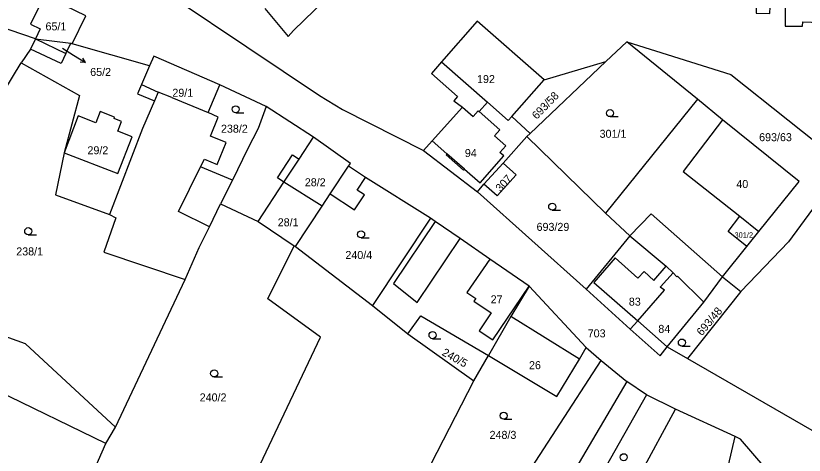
# Model space of a CAD drawing. Extents: x -747333 to -743907, y -1134120 to -1130051.
# Drawn here: x -746528 to -746360.5, y -1132212.3 to -1132118.9 of the extents above; entities that cross this region are included whole.
import ezdxf

# ---------------------------------------------------------------- set-up
doc = ezdxf.new("R2010")
doc.units = 0
for name, color, linetype in [('Hranice parcel', 7, 'Continuous'), ('Parcelní čísla', 7, 'Continuous'), ('Pop  PČ popisy', 7, 'Continuous'), ('Vnitřní kresba', 7, 'Continuous'), ('Značky kultur', 7, 'Continuous')]:
    doc.layers.add(name, color=color, linetype=linetype)

msp = doc.modelspace()

# ---------------------------------------------------------------- linework, layer by layer
at = {"layer": 'Hranice parcel'}
for p, q in [((-746523.8, -1132123.84), (-746533.15, -1132120.64)), ((-746523.8, -1132123.84), (-746524.84, -1132126.03)), ((-746523.8, -1132123.84), (-746516.28, -1132124.76)), ((-746516.28, -1132124.76), (-746515.99, -1132124.9)), ((-746499.55, -1132129.55), (-746515.99, -1132124.9)), ((-746398.24, -1132124.43), (-746402.67, -1132128.64)), ((-746383.2, -1132136.66), (-746398.24, -1132124.43)), ((-746398.24, -1132124.43), (-746376.13, -1132131.39)), ((-746524.84, -1132126.03), (-746526.85, -1132128.93)), ((-746402.67, -1132128.64), (-746418.74, -1132143.92)), ((-746415.8, -1132132.54), (-746402.67, -1132128.64)), ((-746474.8, -1132138.2), (-746484.6, -1132133.59)), ((-746422.65, -1132140.36), (-746415.8, -1132132.54)), ((-746383.2, -1132136.66), (-746402.78, -1132160.86)), ((-746464.75, -1132144.73), (-746474.8, -1132138.2)), ((-746433.12, -1132138.33), (-746439.53, -1132145.49)), ((-746418.74, -1132143.92), (-746422.65, -1132140.36)), ((-746419.45, -1132144.58), (-746418.74, -1132143.92)), ((-746439.53, -1132145.49), (-746441.38, -1132147.52)), ((-746424.49, -1132150.27), (-746419.45, -1132144.58)), ((-746419.45, -1132144.58), (-746402.78, -1132160.86)), ((-746441.38, -1132147.52), (-746429.95, -1132156.33)), ((-746428.57, -1132154.69), (-746424.49, -1132150.27)), ((-746481.98, -1132153.82), (-746484.47, -1132158.9)), ((-746439.9, -1132161.92), (-746453.69, -1132153.29)), ((-746429.95, -1132156.33), (-746428.57, -1132154.69)), ((-746370.18, -1132164.75), (-746361.64, -1132154.17)), ((-746429.95, -1132156.33), (-746406.86, -1132176.98)), ((-746468.6, -1132167.97), (-746462.92, -1132159.41)), ((-746439.9, -1132161.92), (-746452.21, -1132180.46)), ((-746402.78, -1132160.86), (-746397.61, -1132165.68)), ((-746397.61, -1132165.68), (-746406.86, -1132176.98)), ((-746397.61, -1132165.68), (-746389.84, -1132172.12)), ((-746372.76, -1132167.96), (-746370.18, -1132164.75)), ((-746468.85, -1132167.8), (-746468.6, -1132167.97)), ((-746468.6, -1132167.97), (-746452.21, -1132180.46)), ((-746377.93, -1132174.38), (-746372.76, -1132167.96)), ((-746389.84, -1132172.12), (-746388.41, -1132173.53)), ((-746506.79, -1132206.34), (-746492.01, -1132174.94)), ((-746381.9, -1132179.76), (-746377.93, -1132174.38)), ((-746377.93, -1132174.38), (-746374.04, -1132177.52)), ((-746406.82, -1132189.39), (-746418.95, -1132176.36)), ((-746406.86, -1132176.98), (-746397.51, -1132185.52)), ((-746374.04, -1132177.52), (-746385.31, -1132191.74)), ((-746452.21, -1132180.46), (-746444.75, -1132186.48)), ((-746389.67, -1132189.29), (-746381.9, -1132179.76)), ((-746508.81, -1132209.8), (-746568.17, -1132180.98)), ((-746397.51, -1132185.52), (-746395.9, -1132183.77)), ((-746444.75, -1132186.48), (-746430.73, -1132196.48)), ((-746406.82, -1132189.39), (-746403.66, -1132192.14)), ((-746389.67, -1132189.29), (-746385.31, -1132191.74)), ((-746430.73, -1132196.48), (-746427.61, -1132191.08)), ((-746403.66, -1132192.14), (-746398.19, -1132196.61)), ((-746385.31, -1132191.74), (-746349.14, -1132212.69)), ((-746439.77, -1132214.12), (-746430.73, -1132196.48)), ((-746398.19, -1132196.61), (-746414.98, -1132225.06)), ((-746394.06, -1132199.47), (-746398.19, -1132196.61)), ((-746394.06, -1132199.47), (-746409.61, -1132226.97)), ((-746387.86, -1132202.51), (-746394.06, -1132199.47)), ((-746402.53, -1132229.49), (-746387.86, -1132202.51)), ((-746375.2, -1132208.32), (-746387.86, -1132202.51)), ((-746508.81, -1132209.8), (-746506.79, -1132206.34)), ((-746512.76, -1132218.71), (-746508.81, -1132209.8))]:
    msp.add_line(p, q, dxfattribs=at)
for points in [[(-746512.89, -1132094.09), (-746509.52, -1132104.89), (-746463.45, -1132135.88), (-746458.58, -1132138.82), (-746441.38, -1132147.52)], [(-746355.58, -1132109.28), (-746360.59, -1132109.08), (-746360.16, -1132101.31), (-746366.14, -1132100.93), (-746366.2, -1132102.85), (-746370.91, -1132102.78), (-746370.97, -1132104.58), (-746376.22, -1132104.42), (-746376.7, -1132109.89), (-746374.83, -1132110.1), (-746374.9, -1132112.66), (-746370.69, -1132112.9), (-746370.75, -1132118.4), (-746367.87, -1132118.47), (-746367.81, -1132117.06), (-746364.58, -1132117.06), (-746364.61, -1132121.16), (-746360.9, -1132121.16), (-746360.86, -1132120.23), (-746355.36, -1132120.45)], [(-746475.1, -1132117.39), (-746470.12, -1132123.36), (-746469.01, -1132122.04), (-746460.04, -1132113.37)], [(-746515.99, -1132124.9), (-746513.12, -1132118.91), (-746521.86, -1132114.62), (-746524.85, -1132120.71), (-746522.77, -1132121.69), (-746523.8, -1132123.84)], [(-746415.8, -1132132.54), (-746430, -1132120.09), (-746437.54, -1132128.72), (-746439.72, -1132131.22), (-746434.15, -1132136.09), (-746434.93, -1132136.99), (-746433.12, -1132138.33)], [(-746523.8, -1132123.84), (-746517.31, -1132126.95), (-746516.28, -1132124.76)], [(-746543.9, -1132155.07), (-746536.7, -1132145.21), (-746526.85, -1132128.93)], [(-746526.85, -1132128.93), (-746514.46, -1132135.87), (-746517.68, -1132148.02), (-746519.55, -1132156.97), (-746508.03, -1132161.18)], [(-746484.6, -1132133.59), (-746498.66, -1132127.5), (-746499.55, -1132129.55)], [(-746499.55, -1132129.55), (-746501.28, -1132133.56), (-746497.76, -1132135.18), (-746498.53, -1132136.98), (-746501.07, -1132142.89), (-746508.03, -1132161.18)], [(-746376.13, -1132131.39), (-746351.94, -1132150.67), (-746363.92, -1132166.96), (-746374.04, -1132177.52)], [(-746481.98, -1132153.82), (-746488.73, -1132150.99), (-746487.86, -1132149.42), (-746485.17, -1132150.55), (-746483.26, -1132145.87), (-746486.65, -1132144.48), (-746485, -1132140.49), (-746487.14, -1132139.46), (-746484.6, -1132133.59)], [(-746433.12, -1132138.33), (-746430.85, -1132140.35), (-746429.75, -1132139.12), (-746429.6, -1132139.26), (-746427.83, -1132137.27), (-746423.38, -1132141.19), (-746422.65, -1132140.36)], [(-746361.64, -1132154.17), (-746377.92, -1132141.05), (-746383.2, -1132136.66)], [(-746474.8, -1132138.2), (-746476.52, -1132142.87), (-746478.77, -1132147.26), (-746481.98, -1132153.82)], [(-746462.92, -1132159.41), (-746471.01, -1132154.29), (-746467.81, -1132149.4), (-746464.75, -1132144.73)], [(-746453.69, -1132153.29), (-746457.28, -1132150.91), (-746456.89, -1132150.33), (-746464.75, -1132144.73)], [(-746424.49, -1132150.27), (-746421.7, -1132152.74), (-746425.77, -1132157.17), (-746428.57, -1132154.69)], [(-746456.05, -1132160.19), (-746453.92, -1132156.98), (-746455.46, -1132155.96), (-746453.69, -1132153.29)], [(-746462.92, -1132159.41), (-746461.18, -1132156.79), (-746456.05, -1132160.19)], [(-746492.01, -1132174.94), (-746489.02, -1132168.19), (-746486.86, -1132163.77), (-746484.47, -1132158.9)], [(-746484.47, -1132158.9), (-746476.47, -1132162.64), (-746468.85, -1132167.8)], [(-746508.03, -1132161.18), (-746506.73, -1132161.88), (-746509.28, -1132169.18), (-746492.01, -1132174.94)], [(-746433.6, -1132166.24), (-746438.91, -1132162.6), (-746439.9, -1132161.92)], [(-746372.76, -1132167.96), (-746376.72, -1132164.77), (-746374.25, -1132161.52), (-746370.18, -1132164.75)], [(-746418.95, -1132176.36), (-746427.27, -1132170.61), (-746433.6, -1132166.24)], [(-746488.24, -1132239.95), (-746463.28, -1132187.24), (-746474.43, -1132179.05), (-746468.85, -1132167.8)], [(-746395.9, -1132183.77), (-746390.21, -1132177.25), (-746391.15, -1132176.62), (-746391.07, -1132176.53), (-746388.41, -1132173.53)], [(-746388.41, -1132173.53), (-746387.63, -1132174.36), (-746387.45, -1132174.22), (-746381.9, -1132179.76)], [(-746506.79, -1132206.34), (-746525.9, -1132188.66), (-746565.04, -1132174.52)], [(-746418.95, -1132176.36), (-746422.87, -1132182.82), (-746427.61, -1132191.08)], [(-746444.75, -1132186.48), (-746441.98, -1132182.67), (-746427.61, -1132191.08)], [(-746397.51, -1132185.52), (-746391.16, -1132191.17), (-746389.67, -1132189.29)], [(-746427.61, -1132191.08), (-746413.07, -1132199.82), (-746408.27, -1132191.87), (-746406.82, -1132189.39)], [(-746439.77, -1132214.12), (-746422.02, -1132220.4), (-746413.23, -1132206.88), (-746403.66, -1132192.14)], [(-746383.65, -1132246.38), (-746379.95, -1132228.73), (-746375.2, -1132208.32)], [(-746361.01, -1132224.1), (-746374.1, -1132208.89), (-746375.2, -1132208.32)]]:
    msp.add_lwpolyline(points, dxfattribs=at)
at = {"layer": 'Pop  PČ popisy'}
for p, q in [((-746518.05, -1132125.79), (-746515.7, -1132127.28)), ((-746515.7, -1132127.28), (-746513.155, -1132128.87)), ((-746513.155, -1132128.87), (-746514.27, -1132128.764)), ((-746513.155, -1132128.87), (-746513.739, -1132127.915))]:
    msp.add_line(p, q, dxfattribs=at)
at = {"layer": 'Vnitřní kresba'}
for p, q in [((-746518.33, -1132129.1), (-746524.84, -1132126.03)), ((-746517.31, -1132126.95), (-746518.33, -1132129.1)), ((-746437.54, -1132128.72), (-746427.83, -1132137.27)), ((-746501.28, -1132133.56), (-746502.12, -1132135.48)), ((-746502.12, -1132135.48), (-746498.53, -1132136.98)), ((-746494.82, -1132136.26), (-746497.76, -1132135.18)), ((-746494.82, -1132136.26), (-746487.14, -1132139.46)), ((-746514.71, -1132140.21), (-746517.68, -1132148.02)), ((-746510.97, -1132141.65), (-746514.71, -1132140.21)), ((-746510.06, -1132139.27), (-746510.97, -1132141.65)), ((-746506.97, -1132140.46), (-746510.06, -1132139.27)), ((-746507.1, -1132140.78), (-746506.97, -1132140.46)), ((-746429.6, -1132139.26), (-746425.18, -1132143.19)), ((-746505.51, -1132141.4), (-746507.1, -1132140.78)), ((-746506.31, -1132143.45), (-746505.51, -1132141.4)), ((-746377.92, -1132141.05), (-746386.25, -1132151.99)), ((-746503.27, -1132144.62), (-746506.31, -1132143.45)), ((-746425.18, -1132143.19), (-746426.28, -1132144.42)), ((-746506.28, -1132152.42), (-746503.27, -1132144.62)), ((-746439.53, -1132145.49), (-746436.41, -1132148.24)), ((-746426.28, -1132144.42), (-746423.89, -1132146.55)), ((-746425.15, -1132147.97), (-746423.89, -1132146.55)), ((-746517.68, -1132148.02), (-746506.28, -1132152.42)), ((-746472.4, -1132153.39), (-746469.22, -1132148.47)), ((-746469.22, -1132148.47), (-746467.81, -1132149.4)), ((-746436.41, -1132148.24), (-746436.59, -1132148.45)), ((-746436.59, -1132148.45), (-746432.87, -1132151.74)), ((-746432.68, -1132151.53), (-746436.41, -1132148.24)), ((-746429.39, -1132154.44), (-746424.32, -1132148.7)), ((-746424.32, -1132148.7), (-746425.15, -1132147.97)), ((-746493.39, -1132160.49), (-746488.73, -1132150.99)), ((-746461.18, -1132156.79), (-746457.28, -1132150.91)), ((-746432.87, -1132151.74), (-746432.68, -1132151.53)), ((-746432.68, -1132151.53), (-746429.39, -1132154.44)), ((-746386.25, -1132151.99), (-746374.25, -1132161.52)), ((-746471.01, -1132154.29), (-746472.4, -1132153.39)), ((-746476.47, -1132162.64), (-746471.01, -1132154.29)), ((-746486.86, -1132163.77), (-746493.39, -1132160.49)), ((-746393.06, -1132161.01), (-746397.61, -1132165.68)), ((-746377.93, -1132174.38), (-746393.06, -1132161.01)), ((-746438.91, -1132162.6), (-746447.75, -1132175.82)), ((-746442.73, -1132179.87), (-746433.6, -1132166.24)), ((-746400.72, -1132170.37), (-746405.23, -1132175.59)), ((-746395.85, -1132174.69), (-746400.72, -1132170.37)), ((-746392.49, -1132175.17), (-746389.84, -1132172.12)), ((-746394.53, -1132173.23), (-746395.85, -1132174.69)), ((-746392.49, -1132175.17), (-746394.53, -1132173.23)), ((-746405.23, -1132175.59), (-746395.9, -1132183.77)), ((-746447.75, -1132175.82), (-746442.73, -1132179.87)), ((-746408.27, -1132191.87), (-746422.87, -1132182.82)), ((-746395.9, -1132183.77), (-746389.67, -1132189.29))]:
    msp.add_line(p, q, dxfattribs=at)
msp.add_lwpolyline([(-746427.27, -1132170.61), (-746432.16, -1132177.73), (-746430.31, -1132178.99), (-746430.7, -1132179.57), (-746427.03, -1132182.07), (-746429.6, -1132185.84), (-746426.7, -1132187.81), (-746418.95, -1132176.36)], dxfattribs=at)
at = {"layer": 'Značky kultur'}
for p, q in [((-746481.263, -1132139.54), (-746479.513, -1132139.54)), ((-746401.783, -1132140.35), (-746400.033, -1132140.35)), ((-746414.053, -1132160.25), (-746412.303, -1132160.25)), ((-746525.323, -1132165.44), (-746523.573, -1132165.44)), ((-746454.643, -1132166.12), (-746452.893, -1132166.12)), ((-746439.463, -1132187.53), (-746437.713, -1132187.53)), ((-746386.523, -1132189.11), (-746384.773, -1132189.11)), ((-746485.833, -1132195.67), (-746484.083, -1132195.67)), ((-746424.363, -1132204.64), (-746422.613, -1132204.64))]:
    msp.add_line(p, q, dxfattribs=at)
for centre in [(-746481.263, -1132138.79), (-746401.783, -1132139.6), (-746414.053, -1132159.5), (-746525.323, -1132164.69), (-746454.643, -1132165.37), (-746439.463, -1132186.78), (-746386.523, -1132188.36), (-746485.833, -1132194.92), (-746424.363, -1132203.89), (-746398.873, -1132212.72)]:
    msp.add_circle(centre, 0.75, dxfattribs=at)

# ---------------------------------------------------------------- texts
at = {"layer": 'Parcelní čísla'}
for s, height, p in [('65/1', 1.7, (-746521.651, -1132122.03)), ('65/2', 1.7, (-746512.16, -1132131.713)), ('192', 1.7, (-746430.02, -1132133.22)), ('29/1', 1.7, (-746494.71, -1132136.13)), ('238/2', 1.7, (-746484.39, -1132143.77)), ('301/1', 1.7, (-746404, -1132144.85)), ('693/63', 1.7, (-746370.125, -1132145.57)), ('29/2', 1.7, (-746512.74, -1132148.35)), ('94', 1.7, (-746432.61, -1132148.94)), ('28/2', 1.7, (-746466.59, -1132155.15)), ('40', 1.7, (-746374.96, -1132155.52)), ('28/1', 1.7, (-746472.34, -1132163.65)), ('693/29', 1.7, (-746417.38, -1132164.63)), ('301/2', 1.139, (-746375.348, -1132166.079)), ('238/1', 1.7, (-746527.86, -1132169.84)), ('240/4', 1.7, (-746457.97, -1132170.61)), ('27', 1.7, (-746427.13, -1132180.02)), ('83', 1.7, (-746397.79, -1132180.51)), ('703', 1.7, (-746406.52, -1132187.25)), ('84', 1.7, (-746391.53, -1132186.3)), ('26', 1.7, (-746418.99, -1132194.01)), ('240/2', 1.7, (-746488.91, -1132200.86)), ('248/3', 1.7, (-746427.36, -1132208.82))]:
    msp.add_text(s, height=height, dxfattribs=at).set_placement(p)
for s, rotation, p in [('693/58', 46, (-746417.338, -1132141.06)), ('307', 47, (-746425.035, -1132156.474)), ('693/48', 50, (-746382.278, -1132187.046)), ('240/5', 331, (-746437.622, -1132190.953))]:
    msp.add_text(s, height=1.7, rotation=rotation, dxfattribs=at).set_placement(p)

doc.saveas('drawing.dxf')
